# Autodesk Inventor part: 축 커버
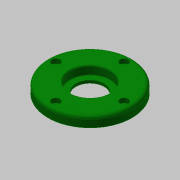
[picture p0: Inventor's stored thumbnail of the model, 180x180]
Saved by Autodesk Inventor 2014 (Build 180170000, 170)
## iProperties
Created: 2015-10
Part Number: 축 커버
Document SubType Name: Modeling
Designer: mdu
Density: 2.71 g/cm^3
Material: 알루미늄 6061
Appearance: 진녹색
Mass: 115.032 g
Surface Area: 136.578 cm^2
Volume: 42.4472 cm^3
Author: mdu
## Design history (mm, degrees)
sketch "스케치1"
  geometry: C1 r 40 at (0, 0) reference; C2 r 26 at (0, 0) reference; 1 further point
  node "참조1"
  node "참조2"
extrude "돌출1" new body sketch "스케치1" distance "d0" = 10; taper "d1" = 0 deg
extrude "돌출2" join sketch "스케치1" distance "d2" = 4; taper "d3" = 0 deg
hole "구멍1" diameter "d6" = 27; stored, may be unused: countersink angle "d10" = 90 deg, drill point angle "d12" = 118 deg; dims "d7" = 6, "d8" = 38, "d9" = 8.3, "d11" = 8, "d33" = 10, "d34" = 10
sketch "스케치2"
  geometry: C1 r 20 at (0, 0); 1 further point
  constraints: 1 centre point, 1 coincident
  dimensions: "d13" = 40 diameter of C1
extrude "돌출3" cut sketch "스케치2" distance "d14" = 3; taper "d15" = 0 deg
sketch "스케치3"
  geometry: C1 r 1.621 at (0, 32.5) reference; 1 further point
hole "구멍2" sketch "스케치3" at (0, 32.5) diameter "d16" = 4.5; stored, may be unused: countersink angle "d20" = 90 deg, drill point angle "d22" = 118 deg; dims "d17" = 6, "d18" = 8, "d19" = 4.4, "d21" = 8
fillet "모깎기1" dims "d26" = 3, "d27" = 0.3
chamfer "모따기1" distance "d28" = 1; stored, may be unused: second distance "d29" = 2, angle "d30" = 45 deg
chamfer "모따기2" distance "d31" = 0.8; stored, may be unused: second distance "d32" = 2, angle "d35" = 30 deg
node "솔리드1"
pattern_circular "원형 패턴1" dims angle "d24" = 360 deg
node "참조3"
